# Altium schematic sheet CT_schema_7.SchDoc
size 255 x 245 mm
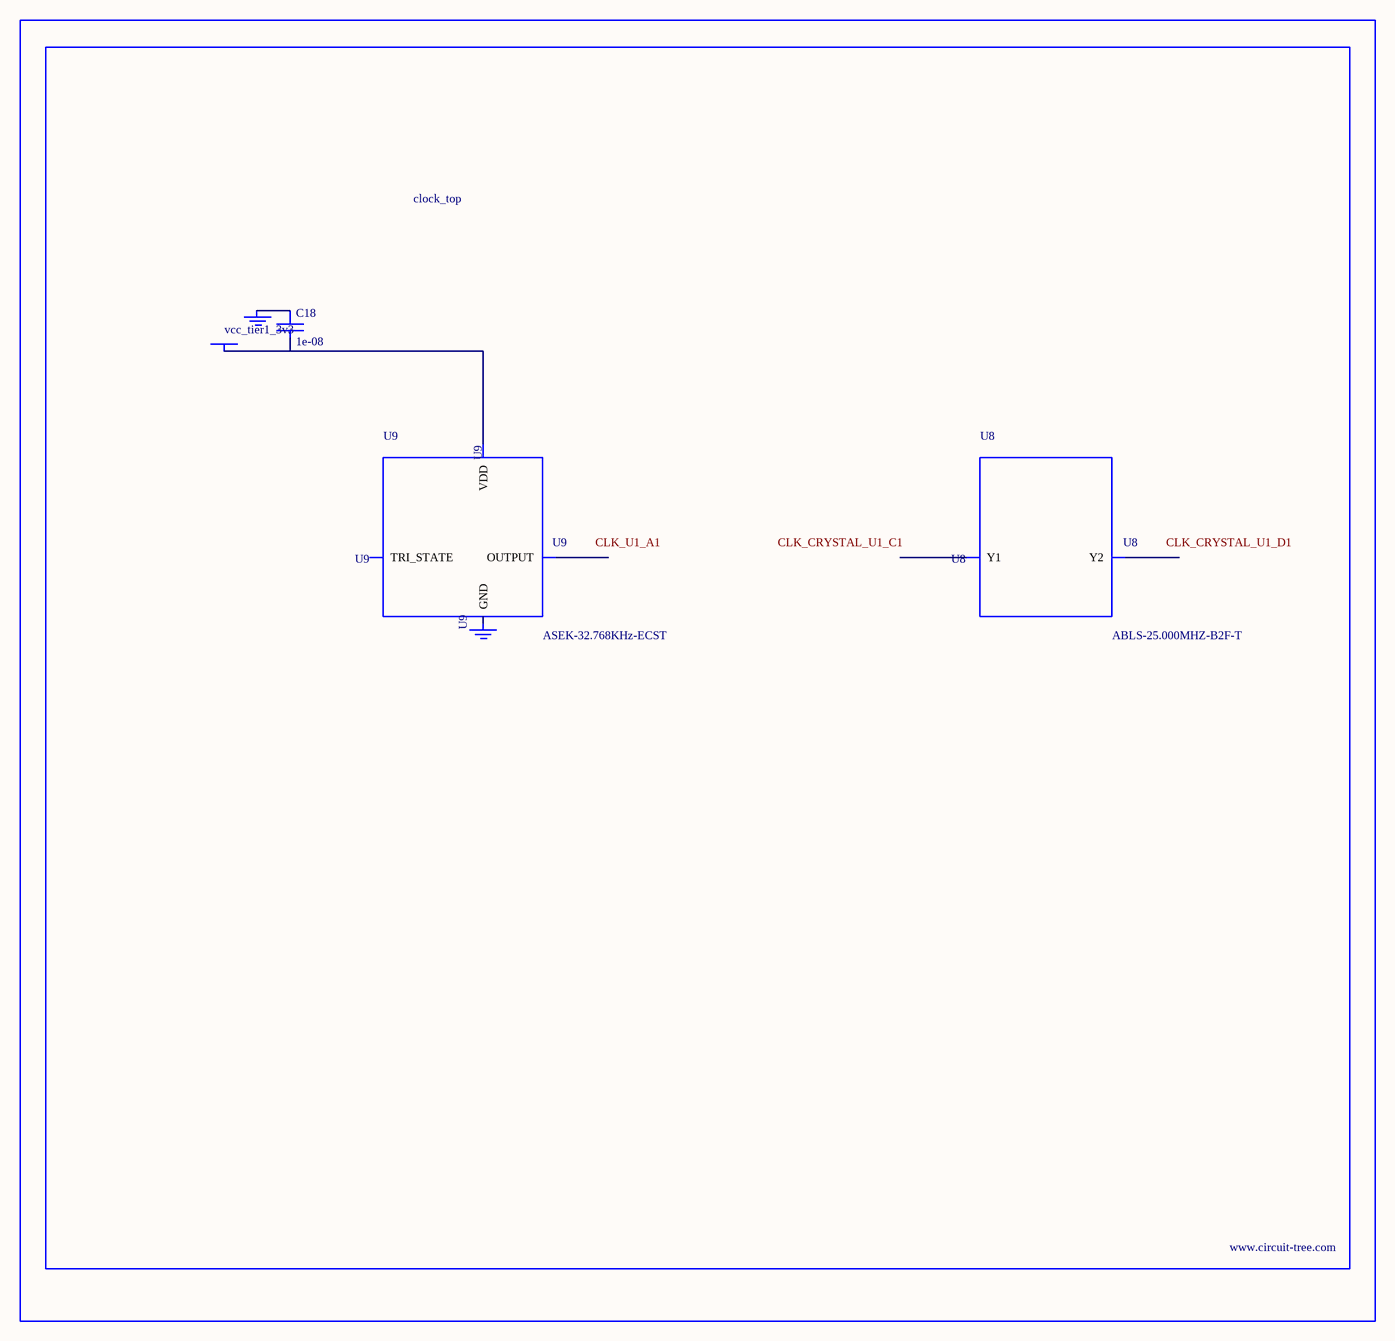
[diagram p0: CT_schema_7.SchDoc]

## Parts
BORDER6  (no value)
C18  1e-08  [C0402]
GND_INSTANCE_6_0  (no value)
GND_INSTANCE_6_1  (no value)
POWER_INSTANCE_6_0  vcc_tier1_3v3
U8  ABLS-25.000MHZ-B2F-T  [ABLS-25.000MHZ-B2F-T]
U9  ASEK-32.768KHz-ECST  [ASEK]

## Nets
NetC18_1: C18.1 GND_INSTANCE_6_0.0(GND)
NetC18_2: C18.2 POWER_INSTANCE_6_0.0(PWR) U9.4(VDD)

Not connected (* = marked no-connect by the designer): GND_INSTANCE_6_1 0(GND); U8 1(Y1) 2(Y2); U9 1(TRI_STATE) 2(GND) 3(OUTPUT)

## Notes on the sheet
- Labels drawn without touching a wire or pin: CLK_CRYSTAL_U1_C1, CLK_CRYSTAL_U1_D1, CLK_U1_A1

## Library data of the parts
BORDER6 = BORDER_PAGE6
C18 = C0402C103K3RAC
GND_INSTANCE_6_0 GND_INSTANCE_6_1 = GND
POWER_INSTANCE_6_0 = PWR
